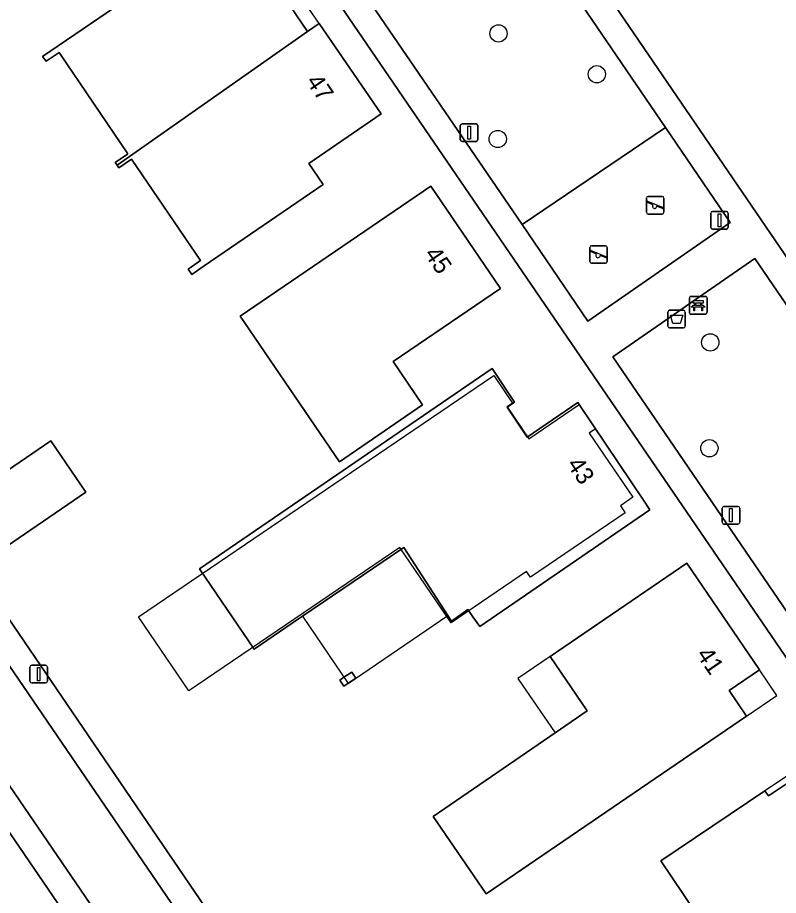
# Model space of a CAD drawing. Extents: x 155275 to 156265, y 382654 to 383635.
# Drawn here: x 155548.86 to 155592.03, y 383140.81 to 383190.6 of the extents above; entities that cross this region are included whole.
import ezdxf

# ---------------------------------------------------------------- set-up
doc = ezdxf.new("R2010")
doc.units = 0
for name, color, linetype in [('IMGEO_Afvalbak', 7, 'Continuous'), ('IMGEO_Bank', 7, 'Continuous'), ('IMGEO_Boom', 7, 'Continuous'), ('IMGEO_Erf', 7, 'Continuous'), ('IMGEO_Groenvoorziening', 7, 'Continuous'), ('IMGEO_Lichtmast', 7, 'Continuous'), ('IMGEO_Pand', 7, 'Continuous'), ('IMGEO_Pand_nummerreeks', 7, 'Continuous'), ('IMGEO_Pand_overbouw', 7, 'Continuous'), ('IMGEO_Pand_vergunning_verleend', 7, 'Continuous'), ('IMGEO_Rijbaan_lokaal_open', 7, 'Continuous'), ('IMGEO_Speelvoorziening', 7, 'Continuous'), ('IMGEO_Terreindeel_onvherhard', 7, 'Continuous'), ('IMGEO_Voetpad_open', 7, 'Continuous')]:
    doc.layers.add(name, color=color, linetype=linetype)

msp = doc.modelspace()

# ---------------------------------------------------------------- linework, layer by layer
at = {"layer": 'IMGEO_Afvalbak'}
for p, q in [((155585.75, 383173.099), (155585.75, 383173.899)), ((155585.75, 383173.899), (155585.75, 383173.099)), ((155585.85, 383173.999), (155586.64, 383173.999)), ((155586.64, 383173.999), (155585.85, 383173.999)), ((155586.74, 383173.899), (155586.74, 383173.099)), ((155586.74, 383173.099), (155586.74, 383173.899)), ((155586.64, 383172.999), (155585.85, 383172.999)), ((155585.85, 383172.999), (155586.64, 383172.999))]:
    msp.add_line(p, q, dxfattribs=at)
msp.add_lwpolyline([(155585.893, 383173.713), (155586.597, 383173.713), (155586.448, 383173.243), (155586.042, 383173.243), (155585.893, 383173.713)], dxfattribs=at)
for centre, start, end in [((155585.85, 383173.899), 90, 180), ((155585.85, 383173.899), 90, 180), ((155586.64, 383173.899), 0, 90), ((155586.64, 383173.899), 360, 90), ((155585.85, 383173.099), 180, 270), ((155585.85, 383173.099), 180, 270), ((155586.64, 383173.099), 270, 0), ((155586.64, 383173.099), 270, 0)]:
    msp.add_arc(centre, 0.1, start, end, dxfattribs=at)
at = {"layer": 'IMGEO_Bank'}
for p, q in [((155586.973, 383173.856), (155586.973, 383174.697)), ((155586.973, 383174.697), (155586.973, 383173.856)), ((155587.048, 383174.781), (155587.889, 383174.781)), ((155587.889, 383174.781), (155587.048, 383174.781)), ((155587.973, 383174.706), (155587.973, 383173.865)), ((155587.973, 383173.865), (155587.973, 383174.706)), ((155587.67, 383174.179), (155587.277, 383174.179)), ((155587.282, 383174.287), (155587.282, 383174.393)), ((155587.326, 383174.393), (155587.326, 383174.287)), ((155587.614, 383174.399), (155587.332, 383174.399)), ((155587.332, 383174.281), (155587.614, 383174.281)), ((155587.62, 383174.287), (155587.62, 383174.393)), ((155587.664, 383174.393), (155587.664, 383174.287)), ((155587.898, 383173.781), (155587.057, 383173.781)), ((155587.057, 383173.781), (155587.898, 383173.781))]:
    msp.add_line(p, q, dxfattribs=at)
for points in [[(155587.22, 383174.179), (155587.078, 383174.179), (155587.19, 383174.281), (155587.276, 383174.281)], [(155587.276, 383174.399), (155587.19, 383174.399), (155587.19, 383174.56), (155587.753, 383174.56), (155587.753, 383174.399), (155587.67, 383174.399)], [(155587.27, 383174.172), (155587.27, 383173.965), (155587.227, 383173.965), (155587.227, 383174.172)], [(155587.67, 383174.281), (155587.753, 383174.281), (155587.865, 383174.179), (155587.726, 383174.179)], [(155587.72, 383174.172), (155587.72, 383173.965), (155587.676, 383173.965), (155587.676, 383174.172)]]:
    msp.add_lwpolyline(points, dxfattribs=at)
for centre, radius, start, end in [((155587.051, 383174.703), 0.0779, 92.4484, 184.2845), ((155587.051, 383174.703), 0.0779, 92.4484, 184.2845), ((155587.895, 383174.703), 0.0779, 2.4484, 94.2845), ((155587.895, 383174.703), 0.0779, 2.4484, 94.2845), ((155587.22, 383174.172), 0.00671, 2.8957, 87.1043), ((155587.277, 383174.172), 0.00671, 92.8957, 177.1043), ((155587.275, 383174.392), 0.00671, 2.8957, 87.1043), ((155587.275, 383174.288), 0.00671, 272.8957, 357.1043), ((155587.332, 383174.392), 0.00671, 92.8957, 177.1043), ((155587.332, 383174.288), 0.00671, 182.8957, 267.1043), ((155587.614, 383174.392), 0.00671, 2.8957, 87.1043), ((155587.614, 383174.288), 0.00671, 272.8957, 357.1043), ((155587.671, 383174.392), 0.00671, 92.8957, 177.1043), ((155587.671, 383174.288), 0.00671, 182.8957, 267.1043), ((155587.669, 383174.172), 0.00671, 2.8957, 87.1043), ((155587.726, 383174.172), 0.00671, 92.8957, 177.1043), ((155587.051, 383173.859), 0.0779, 182.4484, 274.2845), ((155587.051, 383173.859), 0.0779, 182.4484, 274.2845), ((155587.895, 383173.859), 0.0779, 272.4484, 4.2845), ((155587.895, 383173.859), 0.0779, 272.4484, 4.2845)]:
    msp.add_arc(centre, radius, start, end, dxfattribs=at)
at = {"layer": 'IMGEO_Boom'}
for centre in [(155576.144, 383189.701), (155581.722, 383187.384), (155576.103, 383183.71), (155588.158, 383172.174), (155588.108, 383166.171)]:
    msp.add_circle(centre, 0.489, dxfattribs=at)
at = {"layer": 'IMGEO_Erf'}
for points in [[(155583.923, 383230.311), (155564.944, 383217.349), (155603.025, 383161.596), (155604.389, 383162.527), (155625.107, 383176.674), (155589.111, 383229.212)], [(155599.73, 383140.197), (155601.267, 383141.518), (155600.446, 383142.636), (155554.33, 383210.1), (155526.983, 383191.422)], [(155526.277, 383188.898), (155570.403, 383124.152), (155564.804, 383120.367), (155520.794, 383184.782)]]:
    msp.add_lwpolyline(points, dxfattribs=at)
for points in [[(155555.317, 383182.56), (155554.604, 383182.082), (155554.503, 383182.227), (155554.402, 383182.37), (155555.094, 383182.855), (155555.111, 383182.866), (155551.221, 383188.626), (155550.477, 383188.122), (155550.271, 383188.401), (155557.075, 383193.052), (155557.895, 383191.856), (155562.009, 383194.67), (155565.301, 383189.813), (155565.966, 383190.259), (155569.486, 383185.136), (155565.379, 383182.329), (155566.202, 383181.129), (155559.451, 383176.51), (155558.744, 383176.025), (155558.537, 383176.326), (155559.245, 383176.812)], [(155572.305, 383181.038), (155576.257, 383175.241), (155570.16, 383171.087), (155571.838, 383168.633), (155567.133, 383165.409), (155561.497, 383173.657)], [(155559.176, 383159.337), (155575.781, 383170.69), (155577.06, 383168.784), (155576.64, 383168.503), (155577.777, 383166.809), (155580.653, 383168.76), (155581.542, 383167.435), (155584.365, 383163.231), (155584.736, 383162.679), (155575.079, 383156.067), (155574.696, 383156.611), (155574.405, 383157.023), (155573.475, 383156.368), (155573.275, 383156.677), (155570.777, 383160.546), (155565.034, 383156.649), (155564.803, 383156.492), (155562.276, 383154.778)], [(155550.746, 383166.598), (155552.738, 383163.683), (155546.481, 383159.402), (155544.488, 383162.315)], [(155579.353, 383150.023), (155581.181, 383151.274), (155579.068, 383154.36), (155586.828, 383159.651), (155590.952, 383153.598), (155589.225, 383152.421), (155590.216, 383150.966), (155575.439, 383140.889), (155572.431, 383145.282)], [(155567.137, 383153.019), (155567.377, 383153.181), (155567.817, 383153.477), (155568.052, 383153.128), (155567.371, 383152.67)], [(155591.263, 383146.732), (155591.465, 383146.457), (155594.469, 383148.456), (155597.599, 383143.82), (155596.391, 383143.004), (155595.513, 383142.412), (155596.908, 383140.347), (155597.78, 383140.94), (155598.14, 383141.184), (155599.133, 383139.755), (155585.977, 383129.245), (155582.75, 383133.961), (155588.627, 383137.901), (155585.357, 383142.772)]]:
    msp.add_lwpolyline(points, close=True, dxfattribs=at)
at = {"layer": 'IMGEO_Groenvoorziening'}
for points in [[(155563.71, 383216.506), (155555.557, 383210.938), (155577.49, 383178.854), (155585.619, 383184.371)], [(155590.692, 383176.929), (155582.623, 383171.362), (155601.671, 383143.463), (155602.361, 383142.34), (155610.043, 383148.625), (155609.791, 383149.013)]]:
    msp.add_lwpolyline(points, close=True, dxfattribs=at)
at = {"layer": 'IMGEO_Lichtmast'}
for p, q in [((155574.078, 383184.572), (155574.868, 383184.572)), ((155574.868, 383184.572), (155574.078, 383184.572)), ((155573.978, 383183.672), (155573.978, 383184.472)), ((155573.978, 383184.472), (155573.978, 383183.672)), ((155574.968, 383184.472), (155574.968, 383183.672)), ((155574.968, 383183.672), (155574.968, 383184.472)), ((155574.868, 383183.572), (155574.078, 383183.572)), ((155574.078, 383183.572), (155574.868, 383183.572)), ((155588.283, 383179.601), (155589.073, 383179.601)), ((155589.073, 383179.601), (155588.283, 383179.601)), ((155588.183, 383178.701), (155588.183, 383179.501)), ((155588.183, 383179.501), (155588.183, 383178.701)), ((155589.173, 383179.501), (155589.173, 383178.701)), ((155589.173, 383178.701), (155589.173, 383179.501)), ((155589.073, 383178.601), (155588.283, 383178.601)), ((155588.283, 383178.601), (155589.073, 383178.601)), ((155588.836, 383161.97), (155588.836, 383162.77)), ((155588.836, 383162.77), (155588.836, 383161.97)), ((155588.936, 383162.87), (155589.726, 383162.87)), ((155589.726, 383162.87), (155588.936, 383162.87)), ((155589.826, 383162.77), (155589.826, 383161.97)), ((155589.826, 383161.97), (155589.826, 383162.77)), ((155589.726, 383161.87), (155588.936, 383161.87)), ((155588.936, 383161.87), (155589.726, 383161.87)), ((155549.562, 383152.962), (155549.562, 383153.762)), ((155549.562, 383153.762), (155549.562, 383152.962)), ((155549.662, 383153.862), (155550.452, 383153.862)), ((155550.452, 383153.862), (155549.662, 383153.862)), ((155550.552, 383153.762), (155550.552, 383152.962)), ((155550.552, 383152.962), (155550.552, 383153.762)), ((155550.452, 383152.862), (155549.662, 383152.862)), ((155549.662, 383152.862), (155550.452, 383152.862))]:
    msp.add_line(p, q, dxfattribs=at)
for points in [[(155574.398, 383184.447), (155574.548, 383184.447), (155574.548, 383183.697), (155574.398, 383183.697), (155574.398, 383184.447)], [(155588.603, 383179.476), (155588.753, 383179.476), (155588.753, 383178.726), (155588.603, 383178.726), (155588.603, 383179.476)], [(155589.256, 383162.745), (155589.406, 383162.745), (155589.406, 383161.995), (155589.256, 383161.995), (155589.256, 383162.745)], [(155549.982, 383153.737), (155550.132, 383153.737), (155550.132, 383152.987), (155549.982, 383152.987), (155549.982, 383153.737)]]:
    msp.add_lwpolyline(points, dxfattribs=at)
for centre, start, end in [((155574.078, 383184.472), 90, 180), ((155574.078, 383184.472), 90, 180), ((155574.868, 383184.472), 0, 90), ((155574.868, 383184.472), 360, 90), ((155574.078, 383183.672), 180, 270), ((155574.078, 383183.672), 180, 270), ((155574.868, 383183.672), 270, 0), ((155574.868, 383183.672), 270, 0), ((155588.283, 383179.501), 90, 180), ((155588.283, 383179.501), 90, 180), ((155589.073, 383179.501), 0, 90), ((155589.073, 383179.501), 360, 90), ((155588.283, 383178.701), 180, 270), ((155588.283, 383178.701), 180, 270), ((155589.073, 383178.701), 270, 0), ((155589.073, 383178.701), 270, 0), ((155588.936, 383162.77), 90, 180), ((155588.936, 383162.77), 90, 180), ((155589.726, 383162.77), 0, 90), ((155589.726, 383162.77), 360, 90), ((155588.936, 383161.97), 180, 270), ((155588.936, 383161.97), 180, 270), ((155589.726, 383161.97), 270, 0), ((155589.726, 383161.97), 270, 0), ((155549.662, 383153.762), 90, 180), ((155549.662, 383153.762), 90, 180), ((155550.452, 383153.762), 0, 90), ((155550.452, 383153.762), 360, 90), ((155549.662, 383152.962), 180, 270), ((155549.662, 383152.962), 180, 270), ((155550.452, 383152.962), 270, 0), ((155550.452, 383152.962), 270, 0)]:
    msp.add_arc(centre, 0.1, start, end, dxfattribs=at)
at = {"layer": 'IMGEO_Pand'}
for points in [[(155565.301, 383189.813), (155562.009, 383194.67), (155557.895, 383191.856), (155557.075, 383193.052), (155550.271, 383188.401), (155550.477, 383188.122), (155551.221, 383188.626), (155555.111, 383182.866), (155555.094, 383182.855), (155554.402, 383182.37), (155554.503, 383182.227)], [(155565.379, 383182.329), (155569.486, 383185.136), (155565.966, 383190.259), (155565.301, 383189.813), (155554.503, 383182.227), (155554.604, 383182.082), (155555.317, 383182.56), (155559.245, 383176.812), (155558.537, 383176.326), (155558.744, 383176.025), (155559.451, 383176.51), (155566.202, 383181.129)], [(155576.257, 383175.241), (155572.305, 383181.038), (155561.497, 383173.657), (155567.133, 383165.409), (155571.838, 383168.633), (155570.16, 383171.087)], [(155581.542, 383167.435), (155580.653, 383168.76), (155577.777, 383166.809), (155576.64, 383168.503), (155577.06, 383168.784), (155575.781, 383170.69), (155559.176, 383159.337), (155562.276, 383154.778), (155564.803, 383156.492), (155565.034, 383156.649), (155570.777, 383160.546), (155573.275, 383156.677), (155573.475, 383156.368), (155574.405, 383157.023), (155574.696, 383156.611), (155575.079, 383156.067), (155584.736, 383162.679), (155584.365, 383163.231)], [(155550.746, 383166.598), (155544.488, 383162.315), (155546.481, 383159.402), (155552.738, 383163.683)], [(155590.952, 383153.598), (155586.828, 383159.651), (155579.068, 383154.36), (155581.181, 383151.274), (155579.353, 383150.023), (155572.431, 383145.282), (155575.439, 383140.889), (155590.216, 383150.966), (155589.225, 383152.421)], [(155568.052, 383153.128), (155567.817, 383153.477), (155567.377, 383153.181), (155567.137, 383153.019), (155567.371, 383152.67)], [(155595.513, 383142.412), (155596.391, 383143.004), (155597.599, 383143.82), (155594.469, 383148.456), (155591.465, 383146.457), (155591.263, 383146.732), (155585.357, 383142.772), (155588.627, 383137.901), (155582.75, 383133.961), (155585.977, 383129.245), (155599.133, 383139.755), (155598.14, 383141.184), (155597.78, 383140.94), (155596.908, 383140.347)]]:
    msp.add_lwpolyline(points, close=True, dxfattribs=at)
at = {"layer": 'IMGEO_Pand_overbouw'}
for points in [[(155565.966, 383190.259), (155562.648, 383195.106), (155562.009, 383194.67), (155565.301, 383189.813)], [(155567.614, 383152.83), (155573.275, 383156.677), (155570.777, 383160.546), (155565.034, 383156.649)], [(155579.353, 383150.023), (155581.181, 383151.274), (155579.068, 383154.36), (155577.242, 383153.107)], [(155590.216, 383150.966), (155591.943, 383152.144), (155590.952, 383153.598), (155589.225, 383152.421)], [(155591.263, 383146.732), (155591.465, 383146.457), (155594.469, 383148.456), (155594.275, 383148.743)]]:
    msp.add_lwpolyline(points, close=True, dxfattribs=at)
at = {"layer": 'IMGEO_Pand_vergunning_verleend'}
msp.add_lwpolyline([(155555.723, 383156.603), (155575.874, 383170.299), (155576.945, 383168.724), (155576.638, 383168.516), (155577.865, 383166.71), (155580.714, 383168.647), (155581.649, 383167.27), (155581.295, 383167.03), (155583.77, 383163.388), (155583.065, 383162.909), (155583.335, 383162.513), (155577.951, 383158.854), (155577.735, 383159.172), (155573.451, 383156.261), (155570.539, 383160.545), (155558.572, 383152.411)], close=True, dxfattribs=at)
at = {"layer": 'IMGEO_Rijbaan_lokaal_open'}
msp.add_lwpolyline([(155522.479, 383184.963), (155565.273, 383122.33), (155568.387, 383124.551), (155525.665, 383187.096)], dxfattribs=at)
at = {"layer": 'IMGEO_Speelvoorziening'}
for p, q in [((155584.536, 383179.554), (155584.536, 383180.354)), ((155584.536, 383180.354), (155584.536, 383179.554)), ((155584.919, 383179.982), (155584.58, 383180.119)), ((155584.605, 383180.179), (155585.481, 383179.826)), ((155584.636, 383180.454), (155585.426, 383180.454)), ((155585.426, 383180.454), (155584.636, 383180.454)), ((155585.526, 383180.354), (155585.526, 383179.554)), ((155585.526, 383179.554), (155585.526, 383180.354)), ((155585.457, 383179.766), (155585.117, 383179.903)), ((155585.426, 383179.454), (155584.636, 383179.454)), ((155584.636, 383179.454), (155585.426, 383179.454)), ((155581.326, 383176.76), (155581.326, 383177.56)), ((155581.326, 383177.56), (155581.326, 383176.76)), ((155581.426, 383177.66), (155582.216, 383177.66)), ((155582.216, 383177.66), (155581.426, 383177.66)), ((155582.316, 383177.56), (155582.316, 383176.76)), ((155582.316, 383176.76), (155582.316, 383177.56)), ((155581.709, 383177.188), (155581.37, 383177.325)), ((155581.395, 383177.385), (155582.271, 383177.032)), ((155582.247, 383176.972), (155581.907, 383177.109)), ((155582.216, 383176.66), (155581.426, 383176.66)), ((155581.426, 383176.66), (155582.216, 383176.66))]:
    msp.add_line(p, q, dxfattribs=at)
for centre, radius, start, end in [((155584.636, 383180.354), 0.1, 90, 180), ((155584.636, 383180.354), 0.1, 90, 180), ((155584.593, 383180.149), 0.0327, 68.078, 248.078), ((155585.426, 383180.354), 0.1, 0, 90), ((155585.426, 383180.354), 0.1, 360, 90), ((155584.636, 383179.554), 0.1, 180, 270), ((155584.636, 383179.554), 0.1, 180, 270), ((155584.998, 383179.892), 0.12, 130.9928, 5.1632), ((155585.426, 383179.554), 0.1, 270, 0), ((155585.426, 383179.554), 0.1, 270, 0), ((155585.469, 383179.796), 0.0327, 248.078, 68.078), ((155581.426, 383177.56), 0.1, 90, 180), ((155581.426, 383177.56), 0.1, 90, 180), ((155582.216, 383177.56), 0.1, 0, 90), ((155582.216, 383177.56), 0.1, 360, 90), ((155581.383, 383177.355), 0.0327, 68.078, 248.078), ((155581.788, 383177.098), 0.12, 130.9928, 5.1632), ((155581.426, 383176.76), 0.1, 180, 270), ((155581.426, 383176.76), 0.1, 180, 270), ((155582.216, 383176.76), 0.1, 270, 0), ((155582.216, 383176.76), 0.1, 270, 0), ((155582.259, 383177.002), 0.0327, 248.078, 68.078)]:
    msp.add_arc(centre, radius, start, end, dxfattribs=at)
at = {"layer": 'IMGEO_Terreindeel_onvherhard'}
msp.add_lwpolyline([(155585.619, 383184.371), (155577.49, 383178.854), (155581.203, 383173.388), (155589.29, 383178.983)], close=True, dxfattribs=at)
at = {"layer": 'IMGEO_Voetpad_open'}
msp.add_lwpolyline([(155590.692, 383176.929), (155609.791, 383149.013), (155610.043, 383148.625), (155611.256, 383149.591), (155611.034, 383149.871), (155603.025, 383161.596), (155564.944, 383217.349), (155563.71, 383216.506), (155585.619, 383184.371), (155589.29, 383178.983), (155581.203, 383173.388), (155577.49, 383178.854), (155555.557, 383210.938), (155554.33, 383210.1), (155600.446, 383142.636), (155601.267, 383141.518), (155602.361, 383142.34), (155601.671, 383143.463), (155582.623, 383171.362)], close=True, dxfattribs=at)
for points in [[(155520.794, 383184.782), (155564.804, 383120.367), (155570.403, 383124.152), (155526.277, 383188.898)], [(155525.665, 383187.096), (155568.387, 383124.551), (155565.273, 383122.33), (155522.479, 383184.963)]]:
    msp.add_lwpolyline(points, dxfattribs=at)

# ---------------------------------------------------------------- texts
at = {"layer": 'IMGEO_Pand_nummerreeks'}
for s, rotation, p in [('47', 304.297, (155565.193, 383186.974)), ('45', 304.2856, (155571.903, 383177.188)), ('43', 303.8788, (155579.993, 383165.257)), ('41', 304.2684, (155587.337, 383154.464))]:
    msp.add_text(s, height=1, rotation=rotation, dxfattribs=at).set_placement(p)

doc.saveas('drawing.dxf')
